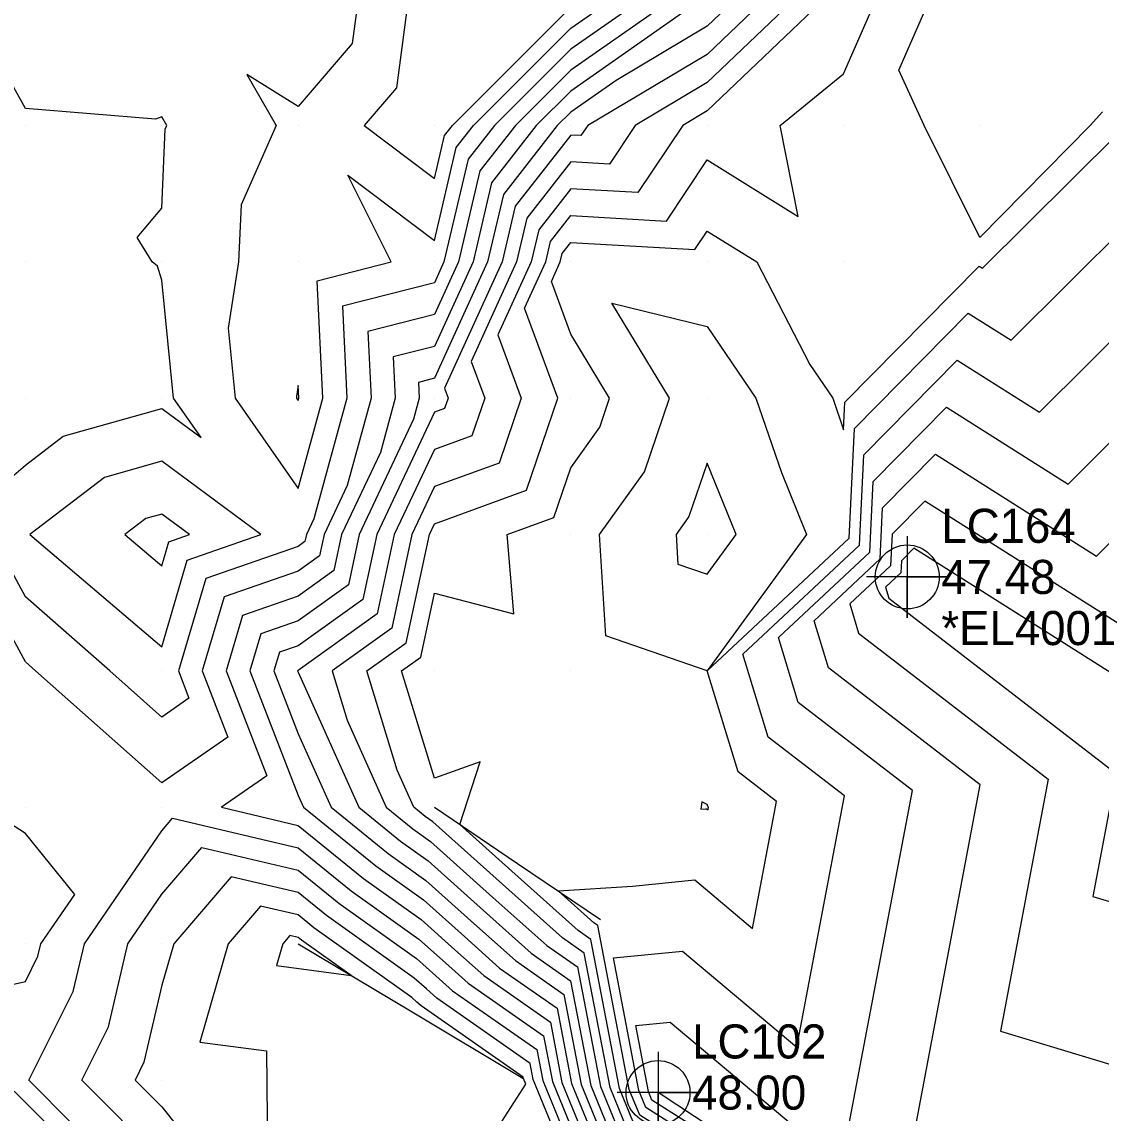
# Model space of a CAD drawing. Extents: x 2188792 to 2191981, y 386090 to 389710.
# Drawn here: x 2189879.8 to 2189959, y 387597.7 to 387677.8 of the extents above; entities that cross this region are included whole.
import ezdxf

# ---------------------------------------------------------------- set-up
doc = ezdxf.new("R2010")
doc.units = 0
for name, color, linetype in [('DTM Contours Major', 7, 'Continuous'), ('DTM Contours Minor', 7, 'Continuous'), ('Exist DTM Breakline Underwater', 7, 'Continuous'), ('Exist DTM Breakline Underwater Cogo Elevation', 7, 'Continuous'), ('Exist DTM Breakline Underwater Cogo Number', 7, 'Continuous'), ('Exist DTM Breakline Underwater Cogo Point CELL', 7, 'Continuous'), ('Exist DTM QL2 LIDAR Elevation Point', 7, 'Continuous'), ('Exist DTM Regular Point Underwater CELL', 7, 'Continuous'), ('Exist DTM Regular Point Underwater Cogo Comment', 7, 'Continuous'), ('Exist DTM Regular Point Underwater Cogo Elevation', 7, 'Continuous'), ('Exist DTM Regular Point Underwater Cogo Number', 7, 'Continuous'), ('PH Exist DTM Breakline', 7, 'Continuous')]:
    doc.layers.add(name, color=color, linetype=linetype)

msp = doc.modelspace()

# ---------------------------------------------------------------- linework, layer by layer
at = {"layer": 'DTM Contours Major'}
for points in [[(2189924.257, 387596.481), (2189922.974, 387599.614), (2189921.077, 387609.469), (2189919.483, 387610.583), (2189915.085, 387614.522), (2189909.973, 387619.1), (2189909.426, 387619.49), (2189908.594, 387620.164), (2189907.372, 387622.89), (2189905.137, 387630.165), (2189908.029, 387632.234), (2189909.729, 387640.166), (2189910.099, 387640.951), (2189916.85, 387643.415), (2189919.152, 387650.166), (2189916.711, 387656.778), (2189918.257, 387660.167), (2189918.608, 387661.66), (2189920.1, 387663.569), (2189927.109, 387663.16), (2189930.101, 387667.646), (2189936.759, 387663.51), (2189935.447, 387670.168), (2189940.102, 387673.96), (2189942.813, 387680.169)], [(2189928.54, 387678.608), (2189920.1, 387672.698), (2189917.568, 387670.168), (2189914.29, 387665.977), (2189912.926, 387660.167), (2189910.099, 387653.971), (2189907.072, 387653.194), (2189907.219, 387650.166), (2189906.131, 387646.199), (2189903.287, 387640.166), (2189902.724, 387637.539), (2189900.098, 387635.66), (2189896.022, 387634.241), (2189894.82, 387630.165), (2189897.794, 387622.467), (2189894.475, 387620.164), (2189900.098, 387618.836), (2189904.89, 387614.955), (2189909.126, 387611.936), (2189911.598, 387609.722), (2189913.725, 387607.817), (2189918.595, 387604.416), (2189919.447, 387599.987), (2189922.017, 387593.714)], [(2189966.148, 387587.407), (2189944.825, 387593.838), (2189950.126, 387621.819), (2189938.989, 387630.402), (2189937.941, 387633.851), (2189942.783, 387638.383), (2189942.963, 387642.134), (2189946.851, 387646.076), (2189958.651, 387638.597), (2189962.844, 387642.767)], [(2189874.191, 387606.067), (2189880.096, 387607.395), (2189881.021, 387609.238), (2189881.234, 387610.163), (2189883.715, 387613.782), (2189880.096, 387618.24), (2189878.935, 387619.002)], [(2189900.355, 387610.42), (2189900.098, 387610.628), (2189899.489, 387610.772), (2189898.966, 387610.163), (2189898.505, 387608.57), (2189903.982, 387607.835), (2189900.355, 387610.42)], [(2189888.904, 387589.678), (2189879.846, 387598.775), (2189879.278, 387599.357)]]:
    msp.add_lwpolyline(points, dxfattribs=at)
at = {"layer": 'DTM Contours Minor'}
for points in [[(2189959.085, 387671.187), (2189958.174, 387670.168), (2189950.103, 387661.966), (2189945.998, 387670.168), (2189944.153, 387674.22), (2189946.751, 387680.169), (2189947.343, 387682.929), (2189948.523, 387690.17), (2189949.614, 387690.659), (2189950.103, 387691.67), (2189958.563, 387691.711), (2189956.771, 387700.171), (2189958.783, 387701.492), (2189960.104, 387702.769)], [(2189928.575, 387680.169), (2189920.1, 387674.235), (2189916.029, 387670.168), (2189913.427, 387666.84), (2189911.86, 387660.167), (2189910.099, 387656.308), (2189905.212, 387655.053), (2189905.451, 387650.166), (2189903.694, 387643.762), (2189901.999, 387640.166), (2189901.664, 387638.6), (2189900.098, 387637.48), (2189894.671, 387635.591), (2189893.072, 387630.165), (2189894.945, 387625.316), (2189890.097, 387621.952), (2189880.851, 387630.165), (2189880.096, 387630.829), (2189875.03, 387640.166)], [(2189877.352, 387642.91), (2189880.096, 387645.264), (2189882.87, 387647.392), (2189890.097, 387649.42), (2189892.979, 387647.284), (2189890.965, 387650.166), (2189890.097, 387658.819), (2189889.78, 387659.85), (2189889.394, 387660.167), (2189888.301, 387661.964), (2189890.097, 387664.115), (2189890.353, 387669.912), (2189890.466, 387670.168), (2189890.097, 387670.814), (2189889.636, 387670.63), (2189880.096, 387671.428), (2189875.244, 387680.169)], [(2189926.38, 387680.169), (2189920.1, 387675.772), (2189914.491, 387670.168), (2189912.564, 387667.704), (2189910.794, 387660.167), (2189910.099, 387658.645), (2189903.353, 387656.912), (2189903.682, 387650.166), (2189901.257, 387641.324), (2189900.711, 387640.166), (2189900.603, 387639.661), (2189900.098, 387639.3), (2189893.321, 387636.942), (2189891.324, 387630.165), (2189892.096, 387628.166), (2189890.097, 387626.779), (2189886.285, 387630.165), (2189880.096, 387635.61), (2189877.624, 387640.166)], [(2189904.591, 387680.169), (2189904.071, 387676.196), (2189900.098, 387671.574), (2189896.345, 387673.921), (2189898.493, 387670.168), (2189895.92, 387664.345), (2189895.736, 387660.167), (2189894.957, 387655.307), (2189895.473, 387650.166), (2189900.098, 387643.549), (2189901.913, 387650.166), (2189901.494, 387658.772), (2189906.928, 387660.167), (2189903.745, 387666.522), (2189910.099, 387661.749), (2189911.7, 387668.567), (2189912.952, 387670.168), (2189920.1, 387677.308), (2189924.185, 387680.169)], [(2189932.927, 387680.169), (2189930.101, 387677.463), (2189923.412, 387673.481), (2189920.1, 387671.161), (2189919.106, 387670.168), (2189915.154, 387665.113), (2189913.992, 387660.167), (2189910.099, 387651.634), (2189908.931, 387651.334), (2189908.988, 387650.166), (2189908.568, 387648.636), (2189904.576, 387640.166), (2189903.785, 387636.478), (2189900.098, 387633.839), (2189897.372, 387632.891), (2189896.568, 387630.165), (2189900.098, 387621.03), (2189900.486, 387620.164), (2189905.797, 387615.862), (2189909.296, 387613.369), (2189912.296, 387610.682), (2189914.877, 387608.37), (2189919.091, 387605.427), (2189920.153, 387599.912), (2189922.465, 387594.267)], [(2189935.094, 387680.169), (2189930.101, 387675.389), (2189921.333, 387670.168), (2189920.84, 387669.429), (2189920.1, 387669.472), (2189916.017, 387664.25), (2189915.058, 387660.167), (2189910.828, 387650.896), (2189911.098, 387650.166), (2189910.844, 387649.422), (2189910.099, 387649.15), (2189905.864, 387640.166), (2189904.846, 387635.417), (2189900.098, 387632.019), (2189898.722, 387631.54), (2189898.317, 387630.165), (2189900.098, 387625.554), (2189902.513, 387620.164), (2189906.704, 387616.769), (2189909.465, 387614.801), (2189912.993, 387611.642), (2189916.029, 387608.923), (2189919.588, 387606.438), (2189920.858, 387599.838), (2189922.913, 387594.821)], [(2189937.26, 387680.169), (2189930.101, 387673.315), (2189924.817, 387670.168), (2189922.929, 387667.339), (2189920.1, 387667.504), (2189916.881, 387663.387), (2189916.125, 387660.167), (2189912.789, 387652.857), (2189913.783, 387650.166), (2189912.846, 387647.419), (2189910.099, 387646.417), (2189907.152, 387640.166), (2189905.907, 387634.356), (2189900.098, 387630.199), (2189900.072, 387630.19), (2189900.065, 387630.165), (2189900.098, 387630.079), (2189904.54, 387620.164), (2189907.611, 387617.676), (2189909.635, 387616.234), (2189913.69, 387612.602), (2189917.18, 387609.476), (2189920.084, 387607.448), (2189921.563, 387599.763), (2189923.361, 387595.374)], [(2189939.427, 387680.169), (2189930.101, 387671.241), (2189928.3, 387670.168), (2189925.019, 387665.249), (2189920.1, 387665.536), (2189917.744, 387662.523), (2189917.191, 387660.167), (2189914.75, 387654.817), (2189916.467, 387650.166), (2189914.848, 387645.417), (2189910.099, 387643.684), (2189908.44, 387640.166), (2189906.968, 387633.295), (2189902.593, 387630.165), (2189903.7, 387626.562), (2189906.567, 387620.164), (2189908.519, 387618.583), (2189909.804, 387617.667), (2189914.388, 387613.562), (2189918.332, 387610.029), (2189920.581, 387608.459), (2189922.269, 387599.688), (2189923.809, 387595.927)], [(2189908.265, 387680.169), (2189907.322, 387672.946), (2189904.934, 387670.168), (2189910.099, 387666.289), (2189910.837, 387669.431)], [(2189910.837, 387669.431), (2189911.414, 387670.168), (2189920.1, 387678.845)], [(2189924.705, 387597.034), (2189923.679, 387599.539), (2189921.574, 387610.48), (2189920.635, 387611.136), (2189915.782, 387615.482), (2189911.955, 387618.909), (2189913.443, 387623.508), (2189910.099, 387622.295), (2189907.68, 387630.165), (2189909.09, 387631.173), (2189910.099, 387635.882), (2189915.916, 387634.349), (2189915.435, 387640.166), (2189918.853, 387641.413), (2189920.1, 387645.071), (2189922.217, 387648.049), (2189922.943, 387650.166), (2189920.1, 387654.871), (2189918.672, 387658.739), (2189919.323, 387660.167), (2189919.471, 387660.796), (2189920.1, 387661.601), (2189929.198, 387661.07), (2189930.101, 387662.423), (2189933.733, 387660.167), (2189937.628, 387652.641), (2189939.3, 387650.166), (2189940.102, 387647.852), (2189940.2, 387649.891), (2189950.032, 387659.862), (2189950.288, 387659.7), (2189960.168, 387669.523)], [(2189963.485, 387573.19), (2189942.561, 387586.464), (2189937.309, 387589.866), (2189925.154, 387597.587), (2189924.384, 387599.464), (2189922.07, 387611.491), (2189921.786, 387611.689), (2189919.163, 387614.038), (2189924.613, 387614.381), (2189929.182, 387614.837), (2189933.422, 387611.277), (2189935.186, 387620.584), (2189932.358, 387622.763), (2189930.107, 387630.168), (2189940.503, 387639.899), (2189940.891, 387647.952), (2189949.237, 387656.416), (2189952.378, 387654.425), (2189960.837, 387662.834)], [(2189930.101, 387630.182), (2189922.671, 387632.735), (2189922.211, 387640.166), (2189925.49, 387644.777), (2189927.337, 387650.166), (2189923.115, 387657.152), (2189930.101, 387655.422), (2189933.653, 387650.166), (2189935.536, 387644.732), (2189937.374, 387640.166), (2189930.101, 387630.182)], [(2189965.289, 387572.91), (2189942.207, 387587.553), (2189939.028, 387589.612), (2189925.602, 387598.14), (2189925.09, 387599.39), (2189923.218, 387609.115), (2189928.283, 387609.62), (2189936.675, 387602.572), (2189940.166, 387620.996), (2189934.568, 387625.31), (2189932.719, 387631.395), (2189941.263, 387639.393), (2189941.582, 387646.012), (2189948.441, 387652.969), (2189954.469, 387649.149), (2189961.506, 387656.145)], [(2189900.144, 387650.166), (2189900.098, 387651.11), (2189899.968, 387650.297), (2189899.981, 387650.166), (2189900.098, 387649.999), (2189900.144, 387650.166)], [(2189959.426, 387577.494), (2189941.853, 387588.642), (2189940.747, 387589.358), (2189926.05, 387598.694), (2189925.795, 387599.315), (2189924.864, 387604.152), (2189927.383, 387604.403), (2189939.928, 387593.868), (2189945.146, 387621.407), (2189936.778, 387627.856), (2189935.33, 387632.623), (2189942.023, 387638.888), (2189942.272, 387644.073), (2189947.646, 387649.523), (2189956.56, 387643.873), (2189962.175, 387649.456)], [(2189891.971, 387638.292), (2189897.355, 387640.166), (2189890.097, 387645.544), (2189885.897, 387644.365), (2189880.424, 387640.166), (2189890.097, 387631.935), (2189891.971, 387638.292)], [(2189930.101, 387645.41), (2189928.762, 387641.504), (2189927.811, 387640.166), (2189927.944, 387638.009), (2189930.101, 387637.268), (2189932.212, 387640.166), (2189930.101, 387645.41)], [(2189960.741, 387633.322), (2189946.055, 387642.63), (2189943.654, 387640.195), (2189943.543, 387637.878), (2189940.552, 387635.078), (2189941.199, 387632.948), (2189955.107, 387622.231), (2189951.602, 387603.735), (2189965.697, 387599.484)], [(2189890.62, 387639.642), (2189892.124, 387640.166), (2189890.097, 387641.668), (2189888.924, 387641.338), (2189887.396, 387640.166), (2189890.097, 387637.867), (2189890.62, 387639.642)], [(2189962.832, 387628.046), (2189945.26, 387639.183), (2189944.345, 387638.255), (2189944.302, 387637.373), (2189943.163, 387636.306), (2189943.41, 387635.494), (2189960.087, 387622.643), (2189958.379, 387613.632), (2189965.246, 387611.561)], [(2189930.205, 387620.172), (2189930.147, 387620.217), (2189930.101, 387620.37), (2189929.707, 387620.557), (2189929.621, 387620.022), (2189929.988, 387620.045), (2189930.082, 387620.054), (2189930.169, 387619.981), (2189930.205, 387620.172)], [(2189890.097, 387590.326), (2189880.357, 387600.162), (2189883.612, 387606.647), (2189884.422, 387610.163), (2189890.097, 387618.441), (2189890.893, 387619.367), (2189900.098, 387617.195), (2189903.983, 387614.048), (2189908.957, 387610.503), (2189910.901, 387608.762), (2189912.574, 387607.264), (2189918.098, 387603.406), (2189918.742, 387600.062), (2189921.569, 387593.161)], [(2189890.097, 387594.255), (2189884.248, 387600.162), (2189886.202, 387604.057), (2189887.61, 387610.163), (2189890.097, 387613.79), (2189893.042, 387617.219), (2189900.098, 387615.553), (2189903.076, 387613.141), (2189908.788, 387609.07), (2189910.204, 387607.802), (2189911.422, 387606.711), (2189917.602, 387602.395), (2189918.037, 387600.136), (2189921.121, 387592.607)], [(2189917.331, 387600.211), (2189917.106, 387601.385), (2189910.271, 387606.158), (2189909.507, 387606.842), (2189908.618, 387607.638), (2189902.169, 387612.234), (2189900.098, 387613.911), (2189895.191, 387615.07), (2189890.976, 387610.163), (2189890.097, 387607.122), (2189888.793, 387601.466), (2189888.138, 387600.162), (2189890.097, 387598.184), (2189896.512, 387590.161), (2189899.253, 387581.005), (2189899.85, 387580.134), (2189899.942, 387580.039), (2189900.034, 387579.929), (2189917.797, 387578.518), (2189906.372, 387583.826), (2189917.764, 387591.68), (2189919.634, 387594.591), (2189917.331, 387600.211)], [(2189916.626, 387600.286), (2189916.609, 387600.374), (2189909.119, 387605.605), (2189908.809, 387605.882), (2189908.449, 387606.205), (2189901.262, 387611.327), (2189900.098, 387612.27), (2189897.34, 387612.921), (2189894.971, 387610.163), (2189892.887, 387602.951), (2189897.778, 387602.295), (2189897.88, 387592.379), (2189899.654, 387590.161), (2189900.098, 387588.676), (2189909.248, 387589.309), (2189910.637, 387590.267), (2189916.799, 387599.863), (2189916.626, 387600.286)]]:
    msp.add_lwpolyline(points, dxfattribs=at)
at = {"layer": 'Exist DTM Breakline Underwater'}
msp.add_lwpolyline([(2190044.846, 387633.972), (2190011.332, 387590.769), (2189992.696, 387560.383), (2189987.062, 387555.03), (2189983.211, 387554.531), (2189966.698, 387572.692), (2189926.493, 387599.241)], dxfattribs=at)
at = {"layer": 'Exist DTM Breakline Underwater Cogo Point CELL'}
msp.add_lwpolyline([(2189926.493, 387602.241), (2189926.493, 387596.241), (2189926.493, 387599.241), (2189929.493, 387599.241), (2189923.493, 387599.241)], dxfattribs=at)
msp.add_circle((2189926.493, 387599.241), 2.344, dxfattribs=at)
at = {"layer": 'Exist DTM QL2 LIDAR Elevation Point'}
for p, q in [((2189880.096, 387670.168), (2189880.096, 387670.168)), ((2189890.097, 387670.168), (2189890.097, 387670.168)), ((2189900.098, 387670.168), (2189900.098, 387670.168)), ((2189910.099, 387670.168), (2189910.099, 387670.168)), ((2189920.1, 387670.168), (2189920.1, 387670.168)), ((2189930.101, 387670.168), (2189930.101, 387670.168)), ((2189940.102, 387670.168), (2189940.102, 387670.168)), ((2189950.103, 387670.168), (2189950.103, 387670.168)), ((2189880.096, 387660.167), (2189880.096, 387660.167)), ((2189890.097, 387660.167), (2189890.097, 387660.167)), ((2189900.098, 387660.167), (2189900.098, 387660.167)), ((2189910.099, 387660.167), (2189910.099, 387660.167)), ((2189920.1, 387660.167), (2189920.1, 387660.167)), ((2189930.101, 387660.167), (2189930.101, 387660.167)), ((2189940.102, 387660.167), (2189940.102, 387660.167)), ((2189950.103, 387660.167), (2189950.103, 387660.167)), ((2189880.096, 387650.166), (2189880.096, 387650.166)), ((2189890.097, 387650.166), (2189890.097, 387650.166)), ((2189900.098, 387650.166), (2189900.098, 387650.166)), ((2189910.099, 387650.166), (2189910.099, 387650.166)), ((2189920.1, 387650.166), (2189920.1, 387650.166)), ((2189930.101, 387650.166), (2189930.101, 387650.166)), ((2189940.102, 387650.166), (2189940.102, 387650.166)), ((2189880.096, 387640.166), (2189880.096, 387640.166)), ((2189890.097, 387640.166), (2189890.097, 387640.166)), ((2189900.098, 387640.166), (2189900.098, 387640.166)), ((2189910.099, 387640.166), (2189910.099, 387640.166)), ((2189920.1, 387640.166), (2189920.1, 387640.166)), ((2189930.101, 387640.166), (2189930.101, 387640.166)), ((2189940.102, 387640.166), (2189940.102, 387640.166)), ((2189880.096, 387630.165), (2189880.096, 387630.165)), ((2189890.097, 387630.165), (2189890.097, 387630.165)), ((2189900.098, 387630.165), (2189900.098, 387630.165)), ((2189910.099, 387630.165), (2189910.099, 387630.165)), ((2189920.1, 387630.165), (2189920.1, 387630.165)), ((2189930.101, 387630.165), (2189930.101, 387630.165)), ((2189880.096, 387620.164), (2189880.096, 387620.164)), ((2189890.097, 387620.164), (2189890.097, 387620.164)), ((2189900.098, 387620.164), (2189900.098, 387620.164)), ((2189930.101, 387620.164), (2189930.101, 387620.164)), ((2189880.096, 387610.163), (2189880.096, 387610.163)), ((2189890.097, 387610.163), (2189890.097, 387610.163)), ((2189880.096, 387600.162), (2189880.096, 387600.162)), ((2189890.097, 387600.162), (2189890.097, 387600.162))]:
    msp.add_line(p, q, dxfattribs=at)
at = {"layer": 'Exist DTM Regular Point Underwater CELL'}
msp.add_lwpolyline([(2189944.77, 387640.062), (2189944.77, 387634.062), (2189944.77, 387637.062), (2189947.77, 387637.062), (2189941.77, 387637.062)], dxfattribs=at)
msp.add_circle((2189944.77, 387637.062), 2.344, dxfattribs=at)
at = {"layer": 'PH Exist DTM Breakline'}
for points in [[(2189910.099, 387620.164), (2189916.192, 387616.046), (2189922.285, 387611.928)], [(2189900.098, 387610.163), (2189908.333, 387605.227), (2189916.569, 387600.292)]]:
    msp.add_lwpolyline(points, dxfattribs=at)

# ---------------------------------------------------------------- texts
at = {"layer": 'Exist DTM Breakline Underwater Cogo Elevation'}
msp.add_text('48.00', height=2.5, dxfattribs=at).set_placement((2189928.993, 387597.991))
at = {"layer": 'Exist DTM Breakline Underwater Cogo Number'}
msp.add_text('LC102', height=2.5, dxfattribs=at).set_placement((2189928.993, 387601.741))
at = {"layer": 'Exist DTM Regular Point Underwater Cogo Comment'}
msp.add_text('*EL4001', height=2.5, dxfattribs=at).set_placement((2189947.27, 387632.062))
at = {"layer": 'Exist DTM Regular Point Underwater Cogo Elevation'}
msp.add_text('47.48', height=2.5, dxfattribs=at).set_placement((2189947.27, 387635.812))
at = {"layer": 'Exist DTM Regular Point Underwater Cogo Number'}
msp.add_text('LC164', height=2.5, dxfattribs=at).set_placement((2189947.27, 387639.562))

doc.saveas('drawing.dxf')
